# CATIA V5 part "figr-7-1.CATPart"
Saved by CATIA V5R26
Part number: Part1
Bounding box of the stored display mesh (mm): x -50 to 50, y -75 to 75, z 0 to 10
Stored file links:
  D:\_Deepak\CATIA\CATIA V5-6R2016_Deepak\Resources\Part files\Partfiles\c07_catia_v5_6r2016_prt\figr-7-1.CATPart
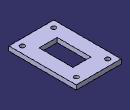
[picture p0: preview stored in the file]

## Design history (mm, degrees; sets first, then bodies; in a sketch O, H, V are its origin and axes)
Body1 (main body)
  Sketch1 on xy-plane, origin (0, 0, 0), H (1, 0, 0), V (0, 1, 0)
    line L1 (-50, 75) -> (50, 75)
    line L2 (50, 75) -> (50, -75)
    line L3 (50, -75) -> (-50, -75)
    line L4 (-50, -75) -> (-50, 75)
    axis line L5 (50, -75) -> (-50, 75)
    length L3 = 100
    length L2 = 150
    horizontal: L1 H, L3 H
    vertical: L2 V, L4 V
    midpoint: O L5
  Pad1: profile Sketch1, direction (0, 0, 1), length 10
  Sketch2 on face of Pad1, origin (0, 0, 10), H (1, 0, 0), V (0, 1, 0)
    line L1 (-20, 37.5) -> (20, 37.5)
    line L2 (20, 37.5) -> (20, -37.5)
    line L3 (20, -37.5) -> (-20, -37.5)
    line L4 (-20, -37.5) -> (-20, 37.5)
    axis line L5 (20, -37.5) -> (-20, 37.5)
    length L3 = 40
    length L2 = 75
    horizontal: L1 H, L3 H
    vertical: L2 V, L4 V
    midpoint: O L5
  Pocket1: profile Sketch2, direction (0, 0, -1), through (limit type 3)
  Sketch3 on face of Pad1, origin (-33.8832, 14.5619, 10), H (1, 0, 0), V (0, 1, 0)
    point P1 (68.8832, -74.5619)
    reference projected line E1 (-16.1168, -89.5619) -> (83.8832, -89.5619) from edge [face of Pad1 | face of Pad1]
    reference projected line E2 (83.8832, -89.5619) -> (83.8832, 60.4381) from edge [face of Pad1 | face of Pad1]
    distance P1 E1 = 15
    distance P1 E2 = 15
  Hole1: placed by Sketch3, at (35, -60, 10) direction (0, 0, -1), diameter 10, through (limit type 3)
  RectPattern1: of Hole1, direction 1 instances 2, spacing 70, along edge [face of Pad1 | face of Pad1] reversed, direction 2 instances 2, spacing 120, along edge [face of Pad1 | face of Pad1]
